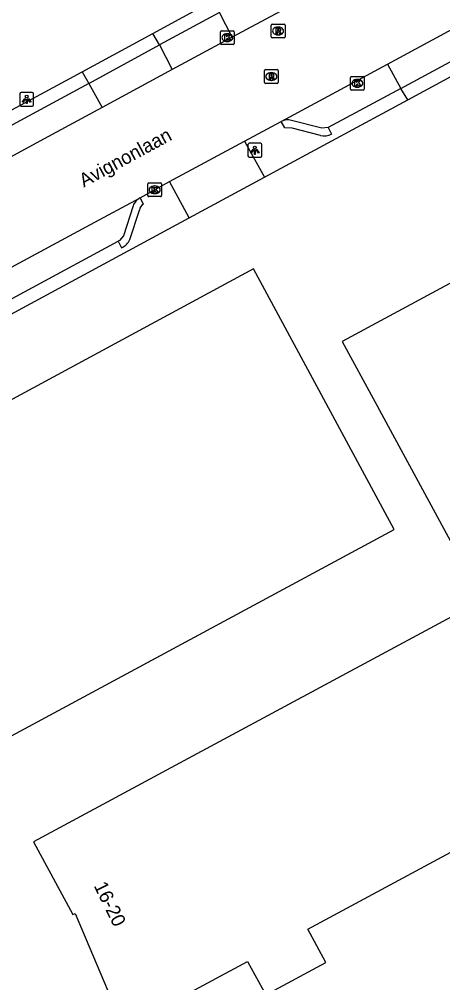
# Model space of a CAD drawing. Extents: x 158461 to 159795, y 387220 to 388672.
# Drawn here: x 158877.8 to 158908.5, y 387484.3 to 387554.1 of the extents above; entities that cross this region are included whole.
import ezdxf

# ---------------------------------------------------------------- set-up
doc = ezdxf.new("R2010")
doc.units = 0
for name, color, linetype in [('IMGEO_Kolk', 7, 'Continuous'), ('IMGEO_Lichtpunt', 7, 'Continuous'), ('IMGEO_Openbare_ruimte_label', 7, 'Continuous'), ('IMGEO_Pand', 7, 'Continuous'), ('IMGEO_Pand_nummerreeks', 7, 'Continuous'), ('IMGEO_Rijbaan_lokaal_gesloten', 7, 'Continuous'), ('IMGEO_Rioolput', 7, 'Continuous'), ('IMGEO_Voetpad_open', 7, 'Continuous')]:
    doc.layers.add(name, color=color, linetype=linetype)

msp = doc.modelspace()

# ---------------------------------------------------------------- linework, layer by layer
at = {"layer": 'IMGEO_Kolk'}
for p, q in [((158892.485, 387553.304), (158893.337, 387553.304)), ((158892.41, 387552.378), (158892.41, 387553.23)), ((158892.898, 387553.084), (158892.923, 387553.084)), ((158893.411, 387553.23), (158893.411, 387552.378)), ((158893.337, 387552.304), (158892.485, 387552.304)), ((158892.921, 387552.524), (158892.896, 387552.524)), ((158901.832, 387549.066), (158901.832, 387549.918)), ((158901.907, 387549.992), (158902.759, 387549.992)), ((158902.833, 387549.918), (158902.833, 387549.066)), ((158902.343, 387549.212), (158902.318, 387549.212)), ((158902.32, 387549.772), (158902.345, 387549.772)), ((158902.759, 387548.992), (158901.907, 387548.992)), ((158887.139, 387541.345), (158887.139, 387542.197)), ((158887.214, 387542.271), (158888.066, 387542.271)), ((158888.14, 387542.197), (158888.14, 387541.345)), ((158887.65, 387541.491), (158887.625, 387541.491)), ((158887.627, 387542.051), (158887.652, 387542.051)), ((158888.066, 387541.271), (158887.214, 387541.271))]:
    msp.add_line(p, q, dxfattribs=at)
for points in [[(158892.485, 387553.304), (158893.337, 387553.304)], [(158892.41, 387552.378), (158892.41, 387553.23)], [(158892.731, 387553.004), (158892.854, 387553.004), (158892.854, 387552.853), (158892.984, 387553.004), (158893.148, 387553.004), (158893.002, 387552.853), (158893.155, 387552.604), (158893.003, 387552.604), (158892.918, 387552.768), (158892.854, 387552.701), (158892.854, 387552.604), (158892.731, 387552.604), (158892.731, 387553.004)], [(158893.411, 387553.23), (158893.411, 387552.378)], [(158893.337, 387552.304), (158892.485, 387552.304)], [(158901.832, 387549.066), (158901.832, 387549.918)], [(158901.907, 387549.992), (158902.759, 387549.992)], [(158902.833, 387549.918), (158902.833, 387549.066)], [(158902.153, 387549.692), (158902.276, 387549.692), (158902.276, 387549.541), (158902.406, 387549.692), (158902.57, 387549.692), (158902.424, 387549.541), (158902.577, 387549.292), (158902.425, 387549.292), (158902.34, 387549.456), (158902.276, 387549.389), (158902.276, 387549.292), (158902.153, 387549.292), (158902.153, 387549.692)], [(158902.759, 387548.992), (158901.907, 387548.992)], [(158887.139, 387541.345), (158887.139, 387542.197)], [(158887.214, 387542.271), (158888.066, 387542.271)], [(158888.14, 387542.197), (158888.14, 387541.345)], [(158887.46, 387541.971), (158887.583, 387541.971), (158887.583, 387541.82), (158887.713, 387541.971), (158887.877, 387541.971), (158887.731, 387541.82), (158887.884, 387541.571), (158887.732, 387541.571), (158887.647, 387541.735), (158887.583, 387541.668), (158887.583, 387541.571), (158887.46, 387541.571), (158887.46, 387541.971)], [(158888.066, 387541.271), (158887.214, 387541.271)]]:
    msp.add_lwpolyline(points, dxfattribs=at)
for centre, start, end in [((158892.487, 387553.228), 91.55205, 178.44795), ((158892.487, 387553.228), 91.55205, 178.44795), ((158893.335, 387553.228), 1.55205, 88.44795), ((158893.335, 387553.228), 1.55205, 88.44795), ((158892.487, 387552.38), 181.55205, 268.44795), ((158892.487, 387552.38), 181.55205, 268.44795), ((158893.335, 387552.38), 271.55205, 358.44795), ((158893.335, 387552.38), 271.55205, 358.44795), ((158901.909, 387549.916), 91.55205, 178.44795), ((158901.909, 387549.916), 91.55205, 178.44795), ((158902.757, 387549.916), 1.55205, 88.44795), ((158902.757, 387549.916), 1.55205, 88.44795), ((158901.909, 387549.068), 181.55205, 268.44795), ((158901.909, 387549.068), 181.55205, 268.44795), ((158902.757, 387549.068), 271.55205, 358.44795), ((158902.757, 387549.068), 271.55205, 358.44795), ((158887.216, 387542.195), 91.55205, 178.44795), ((158887.216, 387542.195), 91.55205, 178.44795), ((158888.064, 387542.195), 1.55205, 88.44795), ((158888.064, 387542.195), 1.55205, 88.44795), ((158887.216, 387541.347), 181.55205, 268.44795), ((158887.216, 387541.347), 181.55205, 268.44795), ((158888.064, 387541.347), 271.55205, 358.44795), ((158888.064, 387541.347), 271.55205, 358.44795)]:
    msp.add_arc(centre, 0.0765, start, end, dxfattribs=at)
for centre, major_axis, ratio, start_param, end_param in [((158892.897, 387552.804), (-0.387, 0.002), 0.722429, 4.712389, 7.853982), ((158892.922, 387552.804), (-0.39, 0.002), 0.717154, 1.570796, 4.712389), ((158902.319, 387549.492), (-0.387, 0.002), 0.722429, 4.712389, 7.853982), ((158902.344, 387549.492), (-0.39, 0.002), 0.717154, 1.570796, 4.712389), ((158887.626, 387541.771), (-0.387, 0.002), 0.722429, 4.712389, 7.853982), ((158887.651, 387541.771), (-0.39, 0.002), 0.717154, 1.570796, 4.712389)]:
    msp.add_ellipse(centre, major_axis=major_axis, ratio=ratio, start_param=start_param, end_param=end_param, dxfattribs=at)
at = {"layer": 'IMGEO_Lichtpunt'}
for p, q in [((158877.866, 387548.737), (158877.866, 387547.93)), ((158877.866, 387548.737), (158877.866, 387547.93)), ((158878.768, 387548.832), (158877.96, 387548.832)), ((158878.768, 387548.832), (158877.96, 387548.832)), ((158878.862, 387547.93), (158878.862, 387548.737)), ((158878.862, 387547.93), (158878.862, 387548.737)), ((158877.96, 387547.836), (158878.768, 387547.836)), ((158877.96, 387547.836), (158878.768, 387547.836)), ((158894.404, 387545.045), (158894.404, 387544.238)), ((158894.404, 387545.045), (158894.404, 387544.238)), ((158895.306, 387545.14), (158894.498, 387545.14)), ((158895.306, 387545.14), (158894.498, 387545.14)), ((158895.4, 387544.238), (158895.4, 387545.045)), ((158895.4, 387544.238), (158895.4, 387545.045)), ((158894.498, 387544.144), (158895.306, 387544.144)), ((158894.498, 387544.144), (158895.306, 387544.144))]:
    msp.add_line(p, q, dxfattribs=at)
for points in [[(158878.24, 387548.401), (158878.279, 387548.373), (158878.091, 387548.111), (158878.053, 387548.138), (158878.24, 387548.401)], [(158878.342, 387548.353), (158878.389, 387548.353), (158878.389, 387548.031), (158878.342, 387548.031), (158878.342, 387548.353)], [(158878.452, 387548.373), (158878.49, 387548.4), (158878.677, 387548.138), (158878.638, 387548.11), (158878.452, 387548.373)], [(158894.778, 387544.709), (158894.817, 387544.681), (158894.629, 387544.419), (158894.591, 387544.446), (158894.778, 387544.709)], [(158894.88, 387544.661), (158894.927, 387544.661), (158894.927, 387544.339), (158894.88, 387544.339), (158894.88, 387544.661)], [(158894.99, 387544.681), (158895.028, 387544.708), (158895.215, 387544.446), (158895.176, 387544.418), (158894.99, 387544.681)]]:
    msp.add_lwpolyline(points, dxfattribs=at)
for centre in [(158878.365, 387548.535), (158894.903, 387544.843)]:
    msp.add_circle(centre, 0.0994, dxfattribs=at)
for centre, start, end in [((158877.96, 387548.737), 90, 180), ((158877.96, 387548.737), 90, 180), ((158878.768, 387548.737), 0, 90), ((158878.768, 387548.737), 0, 90), ((158877.96, 387547.93), 180, 270), ((158877.96, 387547.93), 180, 270), ((158878.768, 387547.93), 270, 0), ((158878.768, 387547.93), 270, 360), ((158894.498, 387545.045), 90, 180), ((158894.498, 387545.045), 90, 180), ((158895.306, 387545.045), 0, 90), ((158895.306, 387545.045), 0, 90), ((158894.498, 387544.238), 180, 270), ((158894.498, 387544.238), 180, 270), ((158895.306, 387544.238), 270, 0), ((158895.306, 387544.238), 270, 360)]:
    msp.add_arc(centre, 0.0946, start, end, dxfattribs=at)
at = {"layer": 'IMGEO_Pand'}
for points in [[(158918.572, 387540.133), (158901.241, 387530.775), (158903.617, 387526.376), (158911.389, 387511.996), (158889.122, 387500), (158883.251, 387496.837), (158878.849, 387494.465), (158881.717, 387489.193), (158881.89, 387489.276), (158885, 387481.898), (158886.246, 387482.453), (158886.683, 387481.656), (158894.367, 387485.79), (158895.687, 387483.369), (158900.055, 387485.717)], [(158865.966, 387508.085), (158867.179, 387508.739), (158871.893, 387500), (158872.202, 387499.427), (158873.264, 387500), (158905.01, 387517.129), (158894.815, 387536.024), (158871.677, 387523.541), (158871.507, 387523.86), (158861.865, 387518.678), (158864.554, 387513.675), (158864.361, 387513.571), (158865.578, 387511.308), (158864.505, 387510.728)], [(158900.055, 387485.717), (158898.749, 387488.149), (158910.681, 387494.573)]]:
    msp.add_lwpolyline(points, dxfattribs=at)
at = {"layer": 'IMGEO_Rijbaan_lokaal_gesloten'}
for points in [[(158901.619, 387557.339), (158893.251, 387552.841)], [(158904.517, 387550.876), (158909.82, 387553.755)], [(158893.251, 387552.841), (158888.915, 387550.505)], [(158888.915, 387550.505), (158883.827, 387547.727)], [(158896.816, 387546.723), (158904.517, 387550.876)], [(158883.827, 387547.727), (158879.639, 387545.462), (158872.408, 387541.551)], [(158894.162, 387545.301), (158896.816, 387546.723)], [(158888.726, 387542.365), (158894.162, 387545.301)], [(158886.59, 387541.192), (158888.726, 387542.365)], [(158856.71, 387525.049), (158882.979, 387539.241), (158886.59, 387541.192)]]:
    msp.add_lwpolyline(points, dxfattribs=at)
at = {"layer": 'IMGEO_Rioolput'}
for p, q in [((158896.088, 387552.861), (158896.088, 387553.713)), ((158896.163, 387553.787), (158897.015, 387553.787)), ((158896.576, 387553.567), (158896.601, 387553.567)), ((158897.089, 387553.713), (158897.089, 387552.861)), ((158897.015, 387552.787), (158896.163, 387552.787)), ((158896.599, 387553.007), (158896.574, 387553.007)), ((158895.595, 387549.557), (158895.595, 387550.409)), ((158895.67, 387550.483), (158896.522, 387550.483)), ((158896.083, 387550.263), (158896.108, 387550.263)), ((158896.596, 387550.409), (158896.596, 387549.557)), ((158896.522, 387549.483), (158895.67, 387549.483)), ((158896.106, 387549.703), (158896.081, 387549.703))]:
    msp.add_line(p, q, dxfattribs=at)
for points in [[(158896.088, 387552.861), (158896.088, 387553.713)], [(158896.163, 387553.787), (158897.015, 387553.787)], [(158896.677, 387553.485), (158896.425, 387553.487), (158896.425, 387553.087)], [(158896.603, 387553.406), (158896.549, 387553.406), (158896.549, 387553.325)], [(158896.549, 387553.325), (158896.601, 387553.325)], [(158897.089, 387553.713), (158897.089, 387552.861)], [(158897.015, 387552.787), (158896.163, 387552.787)], [(158896.425, 387553.087), (158896.549, 387553.087), (158896.549, 387553.249), (158896.56, 387553.249)], [(158896.607, 387553.22), (158896.678, 387553.087), (158896.818, 387553.087), (158896.753, 387553.213)], [(158895.595, 387549.557), (158895.595, 387550.409)], [(158895.67, 387550.483), (158896.522, 387550.483)], [(158896.184, 387550.181), (158895.932, 387550.183), (158895.932, 387549.783)], [(158895.932, 387549.783), (158896.056, 387549.783), (158896.056, 387549.945), (158896.067, 387549.945)], [(158896.11, 387550.102), (158896.056, 387550.102), (158896.056, 387550.021)], [(158896.056, 387550.021), (158896.108, 387550.021)], [(158896.114, 387549.916), (158896.185, 387549.783), (158896.325, 387549.783), (158896.26, 387549.909)], [(158896.596, 387550.409), (158896.596, 387549.557)], [(158896.522, 387549.483), (158895.67, 387549.483)]]:
    msp.add_lwpolyline(points, dxfattribs=at)
for centre, radius, start, end in [((158896.165, 387553.711), 0.0765, 91.55205, 178.44795), ((158896.165, 387553.711), 0.0765, 91.55205, 178.44795), ((158896.585, 387553.514), 0.19, 274.7715, 282.96867), ((158896.609, 387553.31), 0.0964, 77.00612, 93.18647), ((158896.623, 387553.367), 0.0378, 276.66336, 79.67722), ((158896.676, 387553.375), 0.109, 350.36119, 89.41601), ((158896.674, 387553.375), 0.112, 277.58423, 350.98172), ((158897.013, 387553.711), 0.0765, 1.55205, 88.44795), ((158897.013, 387553.711), 0.0765, 1.55205, 88.44795), ((158896.165, 387552.863), 0.0765, 181.55205, 268.44795), ((158896.165, 387552.863), 0.0765, 181.55205, 268.44795), ((158896.559, 387553.196), 0.0533, 26.02933, 88.69889), ((158896.658, 387553.16), 0.108, 29.51342, 73.79051), ((158897.013, 387552.863), 0.0765, 271.55205, 358.44795), ((158897.013, 387552.863), 0.0765, 271.55205, 358.44795), ((158895.672, 387550.407), 0.0765, 91.55205, 178.44795), ((158895.672, 387550.407), 0.0765, 91.55205, 178.44795), ((158896.066, 387549.892), 0.0533, 26.02933, 88.69889), ((158896.092, 387550.21), 0.19, 274.7715, 282.96867), ((158896.116, 387550.006), 0.0964, 77.00612, 93.18647), ((158896.13, 387550.063), 0.0378, 276.66336, 79.67722), ((158896.183, 387550.071), 0.109, 350.36119, 89.41601), ((158896.181, 387550.071), 0.112, 277.58423, 350.98172), ((158896.165, 387549.856), 0.108, 29.51342, 73.79051), ((158896.52, 387550.407), 0.0765, 1.55205, 88.44795), ((158896.52, 387550.407), 0.0765, 1.55205, 88.44795), ((158895.672, 387549.559), 0.0765, 181.55205, 268.44795), ((158895.672, 387549.559), 0.0765, 181.55205, 268.44795), ((158896.52, 387549.559), 0.0765, 271.55205, 358.44795), ((158896.52, 387549.559), 0.0765, 271.55205, 358.44795)]:
    msp.add_arc(centre, radius, start, end, dxfattribs=at)
for centre, major_axis, ratio, start_param, end_param in [((158896.575, 387553.287), (-0.387, 0.002), 0.722429, 4.712389, 7.853982), ((158896.6, 387553.287), (-0.39, 0.002), 0.717154, 1.570796, 4.712389), ((158896.082, 387549.983), (-0.387, 0.002), 0.722429, 4.712389, 7.853982), ((158896.107, 387549.983), (-0.39, 0.002), 0.717154, 1.570796, 4.712389)]:
    msp.add_ellipse(centre, major_axis=major_axis, ratio=ratio, start_param=start_param, end_param=end_param, dxfattribs=at)
at = {"layer": 'IMGEO_Voetpad_open'}
for points in [[(158887.505, 387553.107), (158891.861, 387555.484)], [(158892.333, 387554.624), (158887.982, 387552.279)], [(158893.251, 387552.841), (158892.333, 387554.624)], [(158882.388, 387550.334), (158887.505, 387553.107)], [(158887.982, 387552.279), (158887.505, 387553.107)], [(158882.862, 387549.484), (158887.982, 387552.279)], [(158887.982, 387552.279), (158888.915, 387550.505)], [(158905.479, 387549.127), (158910.792, 387552.002)], [(158904.517, 387550.876), (158905.479, 387549.127)], [(158905.98, 387548.289), (158911.263, 387551.149)], [(158870.999, 387544.18), (158882.388, 387550.334)], [(158882.388, 387550.334), (158882.862, 387549.484)], [(158882.862, 387549.484), (158871.462, 387543.325)], [(158882.862, 387549.484), (158883.827, 387547.727)], [(158905.479, 387549.127), (158900.227, 387546.296)], [(158905.98, 387548.289), (158905.479, 387549.127)], [(158895.605, 387542.69), (158905.98, 387548.289)], [(158899.655, 387545.712), (158897.611, 387546.237), (158897.081, 387546.271), (158896.816, 387546.723)], [(158900.227, 387546.296), (158899.753, 387546.25), (158897.56, 387546.804)], [(158900.227, 387546.296), (158900.455, 387545.797)], [(158894.162, 387545.301), (158895.605, 387542.69)], [(158890.133, 387539.73), (158888.726, 387542.365)], [(158890.133, 387539.73), (158895.605, 387542.69)], [(158886.832, 387540.714), (158886.59, 387541.192)], [(158886.071, 387540.602), (158885.378, 387538.432), (158885.081, 387538.096), (158884.986, 387538.046)], [(158885.849, 387538.166), (158886.534, 387540.301)], [(158856.003, 387521.27), (158890.133, 387539.73)], [(158874.339, 387532.281), (158884.986, 387538.046)], [(158884.986, 387538.046), (158885.248, 387537.557)]]:
    msp.add_lwpolyline(points, dxfattribs=at)
for centre, radius, start, end in [((158897.293, 387545.802), 1.037, 75.06657, 117.36018), ((158899.933, 387546.906), 1.226, 256.9131, 295.21674), ((158887.288, 387540.055), 1.334, 121.53397, 155.79237), ((158887.049, 387540.244), 0.518, 114.74596, 173.62941), ((158884.706, 387538.693), 1.258, 295.50298, 335.25464)]:
    msp.add_arc(centre, radius, start, end, dxfattribs=at)

# ---------------------------------------------------------------- texts
at = {"layer": 'IMGEO_Openbare_ruimte_label'}
msp.add_text('Avignonlaan', height=1, rotation=28.43663, dxfattribs=at).set_placement((158882.506, 387541.922))
at = {"layer": 'IMGEO_Pand_nummerreeks'}
msp.add_text('16-20', height=1, rotation=296.07974, dxfattribs=at).set_placement((158883.205, 387491.296))

doc.saveas('drawing.dxf')
